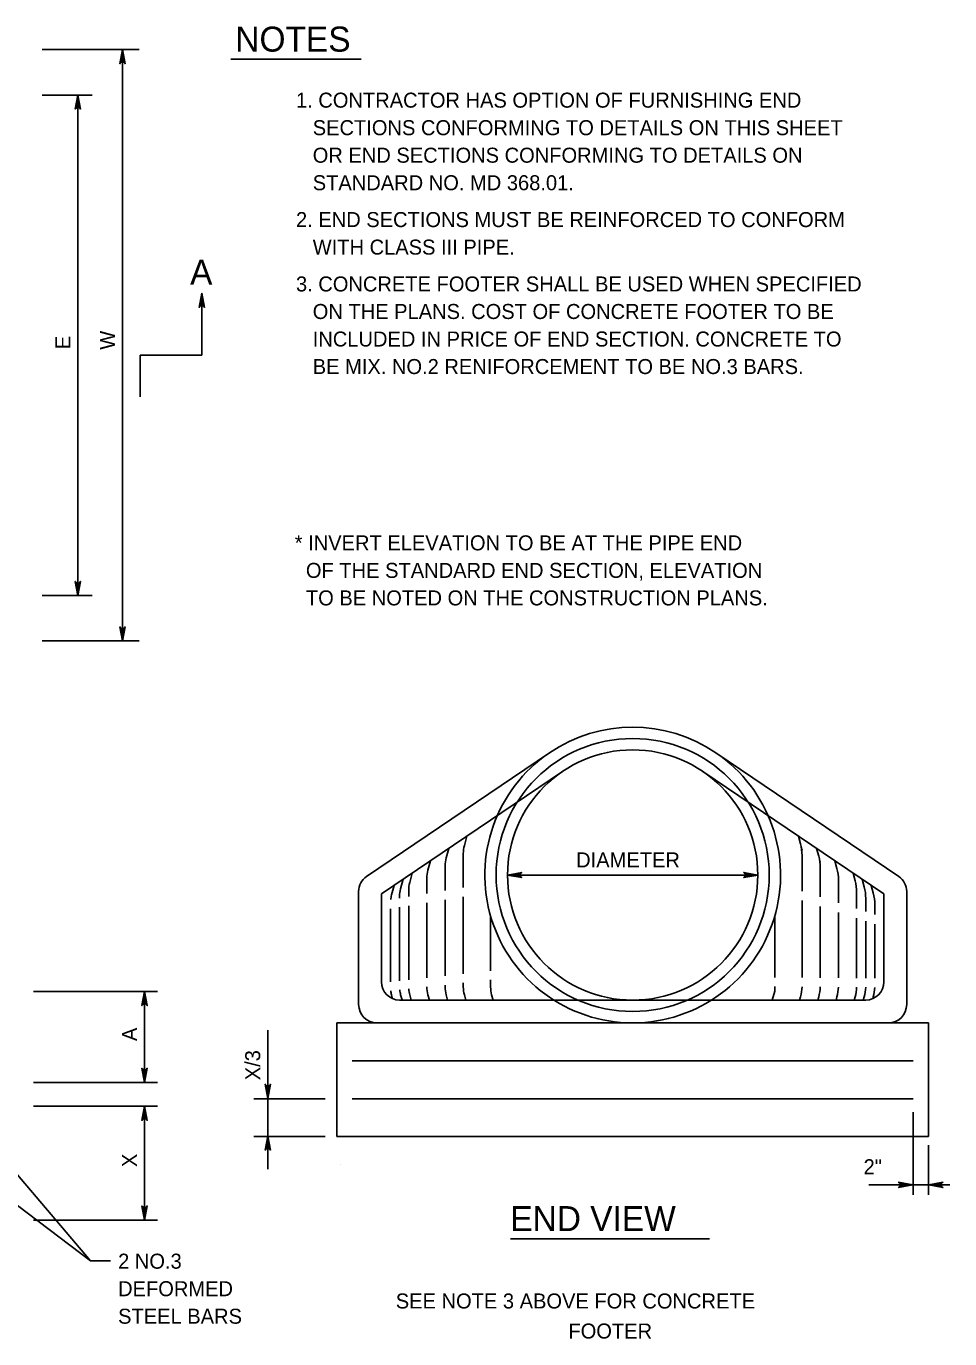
# Model space of a CAD drawing. Extents: x 1 to 8.2, y -2.1 to 8.1.
# Drawn here: x 4.07 to 7.76, y 2.68 to 7.92 of the extents above; entities that cross this region are included whole.
import ezdxf

# ---------------------------------------------------------------- set-up
doc = ezdxf.new("R2010")
doc.units = 0
for name, color, linetype in [('DETL-DIMS', 7, 'Continuous'), ('DETL-LINE', 7, 'Continuous'), ('DETL-NOTE', 7, 'Continuous'), ('DETL-TITL', 7, 'Continuous')]:
    doc.layers.add(name, color=color, linetype=linetype)

msp = doc.modelspace()

# ---------------------------------------------------------------- linework, layer by layer
at = {"layer": 'DETL-DIMS'}
for p, q in [((4.5173, 7.8305), (4.1296, 7.8305)), ((4.4504, 7.8305), (4.4504, 5.4669)), ((4.1296, 7.6487), (4.3298, 7.6487)), ((4.2724, 7.6487), (4.2724, 5.6487)), ((4.7675, 6.6096), (4.7675, 6.8564)), ((4.5207, 6.6096), (4.7675, 6.6096)), ((4.1296, 5.6487), (4.3298, 5.6487)), ((4.5173, 5.4669), (4.1296, 5.4669)), ((5.9889, 4.5316), (6.9889, 4.5316)), ((4.0947, 4.0665), (4.5903, 4.0665)), ((4.5389, 4.0665), (4.5389, 3.7029)), ((5.0311, 3.9118), (5.0311, 3.3556)), ((4.5903, 3.7029), (4.0947, 3.7029)), ((4.9757, 3.6377), (5.2598, 3.6377)), ((4.5903, 3.6073), (4.0947, 3.6073)), ((4.5389, 3.6073), (4.5389, 3.1528)), ((7.6101, 3.5832), (7.6101, 3.2534)), ((4.3231, 2.9891), (3.9085, 3.4763)), ((4.9757, 3.4862), (5.2598, 3.4862)), ((7.6707, 3.2534), (7.6707, 3.4516)), ((5.3198, 3.376), (5.3198, 3.376)), ((3.9112, 3.3004), (4.3231, 2.9891)), ((7.4328, 3.293), (7.7558, 3.293)), ((4.5903, 3.1528), (4.0947, 3.1528)), ((4.3231, 2.9891), (4.4025, 2.9891))]:
    msp.add_line(p, q, dxfattribs=at)
for points in [[(4.4504, 7.8305), (4.461, 7.774), (4.4579, 7.7783), (4.4541, 7.7806), (4.4504, 7.7812), (4.4466, 7.7806), (4.4428, 7.7783), (4.4398, 7.774), (4.4504, 7.8305), (4.4428, 7.7783), (4.4466, 7.7806), (4.4504, 7.8305), (4.4504, 7.7812), (4.4541, 7.7806), (4.4504, 7.8305), (4.4579, 7.7783)], [(4.2724, 7.6487), (4.283, 7.5922), (4.28, 7.5965), (4.2762, 7.5988), (4.2724, 7.5994), (4.2686, 7.5988), (4.2648, 7.5965), (4.2618, 7.5922), (4.2724, 7.6487), (4.2648, 7.5965), (4.2686, 7.5988), (4.2724, 7.6487), (4.2724, 7.5994), (4.2762, 7.5988), (4.2724, 7.6487), (4.28, 7.5965)], [(4.7675, 6.8564), (4.7781, 6.7999), (4.7751, 6.8043), (4.7713, 6.8065), (4.7675, 6.8072), (4.7637, 6.8065), (4.7599, 6.8043), (4.7569, 6.7999), (4.7675, 6.8564), (4.7599, 6.8043), (4.7637, 6.8065), (4.7675, 6.8564), (4.7675, 6.8072), (4.7713, 6.8065), (4.7675, 6.8564), (4.7751, 6.8043)], [(4.2724, 5.6487), (4.2618, 5.7051), (4.2648, 5.7008), (4.2686, 5.6985), (4.2724, 5.6979), (4.2762, 5.6985), (4.28, 5.7008), (4.283, 5.7051), (4.2724, 5.6487), (4.28, 5.7008), (4.2762, 5.6985), (4.2724, 5.6487), (4.2724, 5.6979), (4.2686, 5.6985), (4.2724, 5.6487), (4.2648, 5.7008)], [(4.4504, 5.4669), (4.4398, 5.5233), (4.4428, 5.519), (4.4466, 5.5167), (4.4504, 5.5161), (4.4541, 5.5167), (4.4579, 5.519), (4.461, 5.5233), (4.4504, 5.4669), (4.4579, 5.519), (4.4541, 5.5167), (4.4504, 5.4669), (4.4504, 5.5161), (4.4466, 5.5167), (4.4504, 5.4669), (4.4428, 5.519)], [(5.9889, 4.5316), (6.0454, 4.5422), (6.0411, 4.5392), (6.0388, 4.5354), (6.0382, 4.5316), (6.0388, 4.5278), (6.0411, 4.5241), (6.0454, 4.521), (5.9889, 4.5316), (6.0411, 4.5241), (6.0388, 4.5278), (5.9889, 4.5316), (6.0382, 4.5316), (6.0388, 4.5354), (5.9889, 4.5316), (6.0411, 4.5392)], [(6.9889, 4.5316), (6.9324, 4.521), (6.9368, 4.5241), (6.939, 4.5278), (6.9397, 4.5316), (6.939, 4.5354), (6.9368, 4.5392), (6.9324, 4.5422), (6.9889, 4.5316), (6.9368, 4.5392), (6.939, 4.5354), (6.9889, 4.5316), (6.9397, 4.5316), (6.939, 4.5278), (6.9889, 4.5316), (6.9368, 4.5241)], [(4.5389, 4.0665), (4.5495, 4.01), (4.5465, 4.0144), (4.5427, 4.0166), (4.5389, 4.0173), (4.5351, 4.0166), (4.5313, 4.0144), (4.5283, 4.01), (4.5389, 4.0665), (4.5313, 4.0144), (4.5351, 4.0166), (4.5389, 4.0665), (4.5389, 4.0173), (4.5427, 4.0166), (4.5389, 4.0665), (4.5465, 4.0144)], [(4.5389, 3.7029), (4.5283, 3.7594), (4.5313, 3.755), (4.5351, 3.7528), (4.5389, 3.7521), (4.5427, 3.7528), (4.5465, 3.755), (4.5495, 3.7594), (4.5389, 3.7029), (4.5465, 3.755), (4.5427, 3.7528), (4.5389, 3.7029), (4.5389, 3.7521), (4.5351, 3.7528), (4.5389, 3.7029), (4.5313, 3.755)], [(5.0311, 3.6386), (5.0416, 3.6951), (5.0386, 3.6908), (5.0348, 3.6885), (5.0311, 3.6879), (5.0273, 3.6885), (5.0235, 3.6908), (5.0205, 3.6951), (5.0311, 3.6386), (5.0235, 3.6908), (5.0273, 3.6885), (5.0311, 3.6386), (5.0311, 3.6879), (5.0348, 3.6885), (5.0311, 3.6386), (5.0386, 3.6908)], [(4.5389, 3.6073), (4.5495, 3.5508), (4.5465, 3.5552), (4.5427, 3.5574), (4.5389, 3.5581), (4.5351, 3.5574), (4.5313, 3.5552), (4.5283, 3.5508), (4.5389, 3.6073), (4.5313, 3.5552), (4.5351, 3.5574), (4.5389, 3.6073), (4.5389, 3.5581), (4.5427, 3.5574), (4.5389, 3.6073), (4.5465, 3.5552)], [(5.0311, 3.4885), (5.0416, 3.432), (5.0386, 3.4363), (5.0348, 3.4386), (5.0311, 3.4392), (5.0273, 3.4386), (5.0235, 3.4363), (5.0205, 3.432), (5.0311, 3.4885), (5.0235, 3.4363), (5.0273, 3.4386), (5.0311, 3.4885), (5.0311, 3.4392), (5.0348, 3.4386), (5.0311, 3.4885), (5.0386, 3.4363)], [(7.6082, 3.293), (7.5517, 3.2824), (7.5561, 3.2854), (7.5583, 3.2892), (7.559, 3.293), (7.5583, 3.2968), (7.5561, 3.3005), (7.5517, 3.3036), (7.6082, 3.293), (7.5561, 3.3005), (7.5583, 3.2968), (7.6082, 3.293), (7.559, 3.293), (7.5583, 3.2892), (7.6082, 3.293), (7.5561, 3.2854)], [(7.6722, 3.293), (7.7287, 3.2824), (7.7243, 3.2854), (7.7221, 3.2892), (7.7214, 3.293), (7.7221, 3.2968), (7.7243, 3.3005), (7.7287, 3.3036), (7.6722, 3.293), (7.7243, 3.3005), (7.7221, 3.2968), (7.6722, 3.293), (7.7214, 3.293), (7.7221, 3.2892), (7.6722, 3.293), (7.7243, 3.2854)], [(4.5389, 3.1528), (4.5283, 3.2093), (4.5313, 3.2049), (4.5351, 3.2027), (4.5389, 3.202), (4.5427, 3.2027), (4.5465, 3.2049), (4.5495, 3.2093), (4.5389, 3.1528), (4.5465, 3.2049), (4.5427, 3.2027), (4.5389, 3.1528), (4.5389, 3.202), (4.5351, 3.2027), (4.5389, 3.1528), (4.5313, 3.2049)]]:
    msp.add_lwpolyline(points, dxfattribs=at)
at = {"layer": 'DETL-LINE'}
for p, q in [((4.883, 7.7917), (5.4043, 7.7917)), ((6.1568, 5.0204), (5.4259, 4.5258)), ((6.8211, 5.0204), (7.5519, 4.5258)), ((6.2087, 4.9457), (5.4849, 4.4559)), ((6.7692, 4.9457), (7.493, 4.4559)), ((5.8163, 4.6489), (5.8265, 4.6871)), ((7.1595, 4.6566), (7.1513, 4.6871)), ((5.7436, 4.5997), (5.7538, 4.6379)), ((5.8122, 4.6175), (5.8122, 4.4811)), ((7.2322, 4.6074), (7.224, 4.6379)), ((5.6708, 4.5505), (5.6811, 4.5887)), ((5.7394, 4.5683), (5.7394, 4.4692)), ((7.1657, 4.6095), (7.1657, 4.4673)), ((7.3049, 4.5581), (7.2968, 4.5887)), ((5.5617, 4.4766), (5.572, 4.5148)), ((5.5981, 4.5012), (5.6084, 4.5395)), ((5.6667, 4.5191), (5.6667, 4.4573)), ((7.2384, 4.5603), (7.2384, 4.4439)), ((7.3111, 4.5111), (7.3111, 4.4205)), ((7.3777, 4.5089), (7.3695, 4.5394)), ((7.414, 4.4843), (7.4059, 4.5148)), ((5.394, 4.4656), (5.394, 4.0135)), ((5.5254, 4.452), (5.5356, 4.4902)), ((5.594, 4.4699), (5.594, 4.4454)), ((7.3839, 4.4619), (7.3839, 4.3971)), ((7.4504, 4.4597), (7.4422, 4.4902)), ((7.5839, 4.4655), (7.5839, 4.0135)), ((5.4849, 4.4559), (5.4849, 4.1044)), ((5.5576, 4.4453), (5.5576, 4.4395)), ((5.594, 4.4086), (5.594, 4.1126)), ((5.6667, 4.4205), (5.6667, 4.1206)), ((5.7394, 4.4323), (5.7394, 4.1286)), ((5.8122, 4.4442), (5.8122, 4.1367)), ((7.1657, 4.4291), (7.1657, 4.1215)), ((7.4202, 4.4373), (7.4202, 4.3854)), ((7.4566, 4.4127), (7.4566, 4.3737)), ((7.493, 4.4559), (7.493, 4.1044)), ((5.5213, 4.3967), (5.5213, 4.1045)), ((5.5576, 4.4026), (5.5576, 4.1085)), ((5.9213, 4.3676), (5.9213, 4.1487)), ((7.0566, 4.3676), (7.0566, 4.1225)), ((7.2384, 4.4057), (7.2384, 4.1209)), ((7.3111, 4.3823), (7.3111, 4.1203)), ((7.3839, 4.3589), (7.3839, 4.1197)), ((7.4202, 4.3472), (7.4202, 4.1193)), ((7.4566, 4.3355), (7.4566, 4.119)), ((5.7394, 4.092), (5.7394, 4.084)), ((5.8122, 4.1001), (5.8122, 4.084)), ((5.9213, 4.1121), (5.9213, 4.084)), ((5.5254, 4.0526), (5.5295, 4.0373)), ((5.5617, 4.0526), (5.5672, 4.0323)), ((5.5981, 4.0526), (5.6037, 4.0316)), ((5.6708, 4.0526), (5.6765, 4.0316)), ((5.7436, 4.0526), (5.7492, 4.0316)), ((5.8163, 4.0526), (5.8219, 4.0316)), ((5.9254, 4.0526), (5.931, 4.0316)), ((7.0566, 4.068), (7.0469, 4.0316)), ((7.0566, 4.0861), (7.0566, 4.068)), ((7.1595, 4.0449), (7.1559, 4.0316)), ((7.2322, 4.0449), (7.2287, 4.0316)), ((7.3049, 4.0449), (7.3014, 4.0316)), ((7.3777, 4.0449), (7.3741, 4.0316)), ((7.414, 4.0449), (7.4105, 4.0316)), ((7.4504, 4.0449), (7.4484, 4.0373)), ((5.5576, 4.0316), (7.4202, 4.0316)), ((5.3071, 3.9407), (5.3071, 3.4862)), ((5.3071, 3.9407), (7.6707, 3.9407)), ((7.6707, 3.9407), (7.6707, 3.4862)), ((5.3677, 3.7892), (7.6101, 3.7892)), ((5.3677, 3.6377), (7.6101, 3.6377)), ((5.3071, 3.4862), (7.6707, 3.4862))]:
    msp.add_line(p, q, dxfattribs=at)
for radius in [0.5455, 0.5]:
    msp.add_circle((6.4889, 4.5316), radius, dxfattribs=at)
for centre, radius, start, end in [((6.4889, 4.5316), 0.5909, 55.7989, 124.1933), ((6.4889, 4.5316), 0.5909, 124.1961, 55.7989), ((5.9334, 4.6175), 0.1212, 165.001, 180), ((6.9839, 4.6095), 0.1818, 0, 14.9993), ((6.9839, 4.6095), 0.1818, 0, 15.0013), ((7.1536, 4.6319), 0.0121, 0, 15.0001), ((7.1596, 4.6327), 0.00606, 0, 14.9999), ((7.1606, 4.6328), 0.00505, 0, 15.0002), ((7.1606, 4.6328), 0.00505, 0, 15.0004), ((7.1606, 4.6328), 0.00505, 0, 15.0004), ((5.8606, 4.5683), 0.1212, 164.9993, 180), ((7.0566, 4.5603), 0.1818, 0, 15.0001), ((7.2263, 4.5826), 0.0121, 0, 14.999), ((7.2334, 4.5836), 0.00505, 0, 15.0005), ((5.4667, 4.4656), 0.0727, 124.0872, 180), ((5.7879, 4.5191), 0.1212, 165.0002, 180), ((7.1293, 4.5111), 0.1818, 0, 14.9995), ((7.5111, 4.4655), 0.0727, 0, 55.911), ((5.6788, 4.4453), 0.1212, 164.9997, 180), ((5.7152, 4.4699), 0.1212, 164.9992, 180), ((7.2021, 4.4619), 0.1818, 0, 15), ((7.2384, 4.4373), 0.1818, 0, 14.9992), ((7.2748, 4.4127), 0.1818, 0, 14.9991), ((5.6425, 4.4206), 0.1212, 164.9987, 173.8472), ((5.5576, 4.1044), 0.0727, 180, 270), ((7.4202, 4.1044), 0.0727, 270, 0), ((5.6425, 4.084), 0.1212, 187.5388, 195.0015), ((5.6788, 4.084), 0.1212, 185.651, 195.0009), ((5.7152, 4.084), 0.1212, 183.7627, 195.0006), ((5.7879, 4.084), 0.1212, 179.9751, 194.999), ((5.8606, 4.084), 0.1212, 180, 194.9989), ((5.9334, 4.084), 0.1212, 180, 195.0001), ((6.0425, 4.084), 0.1212, 180, 194.9998), ((6.9839, 4.0919), 0.1818, 344.9987, 357.8666), ((7.0566, 4.0919), 0.1818, 344.9998, 357.6702), ((7.1293, 4.0919), 0.1818, 345.0009, 357.4739), ((7.2021, 4.0919), 0.1818, 344.9995, 357.2763), ((7.2384, 4.0919), 0.1818, 344.9991, 357.1776), ((7.2748, 4.0919), 0.1818, 345.0009, 357.08), ((5.4667, 4.0135), 0.0727, 180, 270), ((7.5111, 4.0135), 0.0727, 270, 0)]:
    msp.add_arc(centre, radius, start, end, dxfattribs=at)
at = {"layer": 'DETL-TITL'}
for p, q in [((4.5207, 6.6096), (4.5207, 6.4423)), ((6.0007, 3.0782), (6.7953, 3.0782))]:
    msp.add_line(p, q, dxfattribs=at)

# ---------------------------------------------------------------- texts
at = {"layer": 'DETL-NOTE'}
for s, height, p in [('NOTES', 0.1, (4.9011, 7.8221)), ('1. CONTRACTOR HAS OPTION OF FURNISHING END', 0.06, (5.1436, 7.5982)), ('   SECTIONS CONFORMING TO DETAILS ON THIS SHEET', 0.06, (5.1436, 7.4882)), ('   OR END SECTIONS CONFORMING TO DETAILS ON', 0.06, (5.1436, 7.3782)), ('   STANDARD NO. MD 368.01.    ', 0.06, (5.1436, 7.2682)), ('2. END SECTIONS MUST BE REINFORCED TO CONFORM', 0.06, (5.1436, 7.1209)), ('   WITH CLASS III PIPE.', 0.06, (5.1436, 7.0109)), ('3. CONCRETE FOOTER SHALL BE USED WHEN SPECIFIED', 0.06, (5.1436, 6.8636)), ('   ON THE PLANS. COST OF CONCRETE FOOTER TO BE', 0.06, (5.1436, 6.7536)), ('   INCLUDED IN PRICE OF END SECTION. CONCRETE TO', 0.06, (5.1436, 6.6436)), ('   BE MIX. NO.2 RENIFORCEMENT TO BE NO.3 BARS.', 0.06, (5.1436, 6.5336)), ('* INVERT ELEVATION TO BE AT THE PIPE END', 0.06, (5.1386, 5.829)), ('  OF THE STANDARD END SECTION, ELEVATION', 0.06, (5.1386, 5.719)), ('  TO BE NOTED ON THE CONSTRUCTION PLANS.', 0.06, (5.1386, 5.609)), ('DIAMETER', 0.06, (6.263, 4.5619)), ('2"', 0.06, (7.4116, 3.3357)), ('2 NO.3', 0.06, (4.4328, 2.9583)), ('DEFORMED ', 0.06, (4.4328, 2.8483)), ('SEE NOTE 3 ABOVE FOR CONCRETE', 0.06, (5.5423, 2.7992)), ('STEEL BARS', 0.06, (4.4328, 2.7383)), ('FOOTER', 0.06, (6.2321, 2.6792))]:
    msp.add_text(s, height=height, dxfattribs=at).set_placement(p)
for s, p in [('E', (4.2421, 6.6329)), ('W', (4.4201, 6.6307)), ('A', (4.5086, 3.868)), ('X/3', (5.0007, 3.7113)), ('X', (4.5086, 3.3643))]:
    msp.add_text(s, height=0.06, rotation=90, dxfattribs=at).set_placement(p)
at = {"layer": 'DETL-TITL'}
for s, p in [('A', (4.7205, 6.8907)), ('END VIEW', (5.9999, 3.1085))]:
    msp.add_text(s, height=0.1, dxfattribs=at).set_placement(p)

doc.saveas('drawing.dxf')
